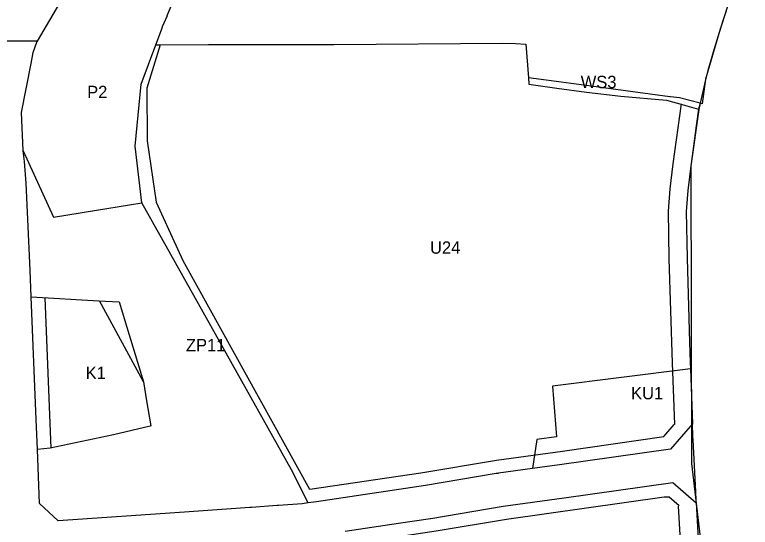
# Model space of a CAD drawing. Extents: x 7428103 to 7431580, y 5545880 to 5549002.
# Drawn here: x 7429886.6 to 7430217.3, y 5548057.7 to 5548288 of the extents above; entities that cross this region are included whole.
import ezdxf

# ---------------------------------------------------------------- set-up
doc = ezdxf.new("R2010")
doc.units = 0
for name, color, linetype in [('CZ_L_linie rozgraniczające tereny o różnym przeznaczeniu oraz różnych warunkach ich zabudowy i zagospodarowania', 7, 'Continuous'), ('CZ_L_maksymalne nieprzekraczalne linie zabudowy', 7, 'Continuous'), ('CZ_L_opisy_linie rozgraniczające tereny o różnym przeznaczeniu oraz różnych warunkach ich zabudowy i zagospodarowania', 7, 'Continuous'), ('Łąki_Nowohuckie', 7, 'Continuous')]:
    doc.layers.add(name, color=color, linetype=linetype)

msp = doc.modelspace()

# ---------------------------------------------------------------- linework, layer by layer
at = {"layer": 'CZ_L_linie rozgraniczające tereny o różnym przeznaczeniu oraz różnych warunkach ich zabudowy i zagospodarowania'}
for p, q in [((7429955.17, 5548287.65), (7429963.28, 5548306.64)), ((7429911.31, 5548300.91), (7429902.3, 5548285.56)), ((7430208.15, 5548295.69), (7430203.82, 5548281.96)), ((7429953.1, 5548282.8), (7429955.31, 5548287.65)), ((7429955.31, 5548287.65), (7429955.17, 5548287.65)), ((7429902.3, 5548285.56), (7429896.76, 5548276.15)), ((7429950.02, 5548274.53), (7429953.08, 5548282.4)), ((7429952.93, 5548282.41), (7429953.07, 5548282.8)), ((7429953.08, 5548282.4), (7429952.93, 5548282.41)), ((7429953.07, 5548282.8), (7429953.1, 5548282.8)), ((7430203.82, 5548281.96), (7430201.1, 5548272.72)), ((7429896.76, 5548276.15), (7429856.01, 5548276.02)), ((7429895.01, 5548271.04), (7429896.76, 5548276.15)), ((7429943.51, 5548256.83), (7429950.02, 5548274.53)), ((7429950.02, 5548274.53), (7429952.04, 5548274.53)), ((7429952.04, 5548274.53), (7429973.7, 5548274.58)), ((7429973.7, 5548274.58), (7430010.32, 5548274.66)), ((7430010.32, 5548274.66), (7430030.1, 5548274.7)), ((7430030.1, 5548274.7), (7430106, 5548275.27)), ((7430106, 5548275.27), (7430111.79, 5548275.03)), ((7430111.79, 5548275.03), (7430116.43, 5548274.83)), ((7430116.43, 5548274.83), (7430117.56, 5548259.73)), ((7429894.04, 5548266.06), (7429895.01, 5548271.04)), ((7430201.1, 5548272.72), (7430198.23, 5548262.99)), ((7429889.76, 5548244.08), (7429894.04, 5548266.06)), ((7430198.23, 5548262.99), (7430197.07, 5548258.75)), ((7430125.5, 5548258.65), (7430117.56, 5548259.73)), ((7430147.99, 5548255.62), (7430125.5, 5548258.65)), ((7430197.07, 5548258.75), (7430194.69, 5548248.36)), ((7429940.84, 5548228.99), (7429943.51, 5548256.83)), ((7430166.77, 5548253.11), (7430147.99, 5548255.62)), ((7430181.07, 5548251.2), (7430166.77, 5548253.11)), ((7430181.45, 5548251.13), (7430181.07, 5548251.2)), ((7430185.4, 5548250.61), (7430181.45, 5548251.13)), ((7430194.69, 5548248.36), (7430185.4, 5548250.61)), ((7430194.69, 5548248.36), (7430194.06, 5548245.59)), ((7429890.38, 5548227.06), (7429889.76, 5548244.08)), ((7430194.06, 5548245.59), (7430193.01, 5548238.09)), ((7430193.01, 5548238.09), (7430191.43, 5548226.76)), ((7429943.82, 5548203.5), (7429940.84, 5548228.99)), ((7429890.5, 5548226.8), (7429890.38, 5548227.06)), ((7429891.04, 5548222), (7429890.5, 5548226.8)), ((7429890.5, 5548226.8), (7429904.1, 5548197.11)), ((7430191.43, 5548226.76), (7430190.5, 5548220.15)), ((7429891.82, 5548212.26), (7429891.04, 5548222)), ((7430190.5, 5548220.15), (7430189.22, 5548209.03)), ((7429893.61, 5548173.2), (7429891.82, 5548212.26)), ((7430189.22, 5548209.03), (7430188.5, 5548199.62)), ((7429923.44, 5548200.17), (7429938.23, 5548202.63)), ((7429938.23, 5548202.63), (7429943.82, 5548203.5)), ((7429953.36, 5548186.48), (7429943.82, 5548203.5)), ((7429904.1, 5548197.11), (7429923.44, 5548200.17)), ((7430188.5, 5548199.62), (7430188.83, 5548178.55)), ((7429980.38, 5548138.29), (7429953.36, 5548186.48)), ((7430188.83, 5548178.55), (7430189.99, 5548140.74)), ((7429894.09, 5548161.22), (7429893.61, 5548173.2)), ((7429896.29, 5548106.13), (7429894.09, 5548161.22)), ((7429894.09, 5548161.22), (7429924.42, 5548159.49)), ((7429924.42, 5548159.49), (7429933.62, 5548158.97)), ((7429933.62, 5548158.97), (7429936.03, 5548150.99)), ((7429936.03, 5548150.99), (7429944.49, 5548123)), ((7430011.07, 5548083.54), (7429980.38, 5548138.29)), ((7430189.99, 5548140.74), (7430190.26, 5548131.75)), ((7430190.26, 5548131.75), (7430190.37, 5548128.86)), ((7430190.37, 5548128.86), (7430128.38, 5548121.04)), ((7430190.37, 5548128.86), (7430191.3, 5548104.13)), ((7429944.49, 5548123), (7429945.82, 5548114.54)), ((7430128.38, 5548121.04), (7430130.16, 5548098.26)), ((7429945.82, 5548114.54), (7429947.79, 5548103.21)), ((7429896.84, 5548092.61), (7429896.29, 5548106.13)), ((7429947.51, 5548103.15), (7429931.08, 5548099.27)), ((7429947.79, 5548103.21), (7429947.51, 5548103.15)), ((7430191.3, 5548104.13), (7430181.44, 5548092.75)), ((7430191.51, 5548098.46), (7430191.3, 5548104.13)), ((7429931.08, 5548099.27), (7429902.65, 5548093.16)), ((7430191.57, 5548096.98), (7430191.51, 5548098.46)), ((7430121.31, 5548097.17), (7430119.43, 5548084.03)), ((7430130.16, 5548098.26), (7430121.31, 5548097.17)), ((7430192.74, 5548073.53), (7430191.57, 5548096.98)), ((7429902.65, 5548093.16), (7429896.84, 5548092.61)), ((7429897.82, 5548068.32), (7429896.84, 5548092.61)), ((7430181.44, 5548092.75), (7430131.58, 5548085.69)), ((7430131.58, 5548085.69), (7430119.43, 5548084.03)), ((7430018.58, 5548068.58), (7430011.07, 5548083.54)), ((7430103.84, 5548081.89), (7430103.02, 5548081.76)), ((7430104.07, 5548081.93), (7430103.84, 5548081.89)), ((7430119.43, 5548084.03), (7430104.07, 5548081.93)), ((7430103.02, 5548081.76), (7430071.3, 5548076.41)), ((7430071.3, 5548076.41), (7430022.24, 5548069.12)), ((7430133.65, 5548070.84), (7430182.38, 5548077.74)), ((7430182.38, 5548077.74), (7430192.99, 5548068.68)), ((7430192.91, 5548070.03), (7430192.74, 5548073.53)), ((7430022.24, 5548069.12), (7430018.58, 5548068.58)), ((7430106.21, 5548067.08), (7430133.62, 5548070.83)), ((7430133.62, 5548070.83), (7430133.65, 5548070.84)), ((7430192.99, 5548068.68), (7430192.91, 5548070.03)), ((7430192.99, 5548068.68), (7430195.61, 5548021.96)), ((7429906.23, 5548060.63), (7429897.82, 5548068.32)), ((7429992.31, 5548066.53), (7429962.95, 5548064.49)), ((7429993.07, 5548066.59), (7429992.31, 5548066.53)), ((7430004.6, 5548067.39), (7429993.07, 5548066.59)), ((7430005.22, 5548067.43), (7430004.6, 5548067.39)), ((7430015.87, 5548068.17), (7430005.22, 5548067.43)), ((7430018.58, 5548068.58), (7430015.87, 5548068.17)), ((7430073.72, 5548061.61), (7430106.21, 5548067.08)), ((7429962.95, 5548064.49), (7429906.23, 5548060.63)), ((7430035.16, 5548055.88), (7430059.1, 5548059.44)), ((7430059.1, 5548059.44), (7430073.57, 5548061.59)), ((7430073.57, 5548061.59), (7430073.72, 5548061.61))]:
    msp.add_line(p, q, dxfattribs=at)
for points in [[(7430117.56, 5548259.73), (7430117.55, 5548259.73)], [(7430117.55, 5548259.73), (7430117.78, 5548256.79), (7430130.25, 5548255.01), (7430143.72, 5548253.16), (7430159.11, 5548251.49), (7430179.63, 5548249.59), (7430186.61, 5548247.65), (7430194.06, 5548245.59)]]:
    msp.add_lwpolyline(points, dxfattribs=at)
at = {"layer": 'CZ_L_maksymalne nieprzekraczalne linie zabudowy'}
for points in [[(7429952.08, 5548274.53), (7429946.08, 5548254.96), (7429946.22, 5548231.33), (7429950.28, 5548203.72), (7429962.18, 5548177.62), (7430019.07, 5548074.85)], [(7430183.3, 5548103.86), (7430182.27, 5548131.5), (7430180.84, 5548178.31), (7430180.5, 5548199.81), (7430181.25, 5548209.75), (7430182.55, 5548221.08), (7430186.4, 5548247.99)], [(7429900.11, 5548160.85), (7429902.82, 5548093.18)], [(7429944.49, 5548123), (7429924.73, 5548159.48)], [(7430019.23, 5548074.74), (7430069.16, 5548082.16), (7430103.17, 5548087.86), (7430132.86, 5548091.93), (7430178.48, 5548098.5), (7430183.12, 5548103.86)], [(7430185.29, 5548067.36), (7430180.79, 5548071.2), (7430178.6, 5548071.14), (7430107.69, 5548061.23), (7430076.06, 5548055.92), (7430039.24, 5548050.42), (7430038.47, 5548048.77), (7430038.85, 5548042.83)], [(7430154.46, 5547785.67), (7430173.26, 5547792.27), (7430193.23, 5547799.51), (7430194.45, 5547800.07), (7430198.73, 5547806.16), (7430199.09, 5547838.74), (7430198.96, 5547850.56), (7430197.64, 5547869.4), (7430193.56, 5547919.92), (7430185.06, 5548067.1)]]:
    msp.add_lwpolyline(points, dxfattribs=at)
at = {"layer": 'Łąki_Nowohuckie'}
for p, q in [((7430203.25, 5548280.01), (7430197.15, 5548259.12)), ((7430197.15, 5548259.12), (7430195.7, 5548248.02)), ((7430194.67, 5548248.27), (7430194.08, 5548245.49)), ((7430195.7, 5548248.02), (7430194.67, 5548248.27)), ((7430194.08, 5548245.49), (7430190.51, 5548220.05)), ((7430190.51, 5548220.05), (7430190.87, 5548086.36))]:
    msp.add_line(p, q, dxfattribs=at)
for points in [[(7430297.2, 5548430.43), (7430238.13, 5548349.75), (7430225.26, 5548330.6), (7430217.87, 5548316.02), (7430208.17, 5548295.59), (7430203.25, 5548280.01)], [(7430190.87, 5548086.36), (7430194.64, 5548054.47), (7430202.16, 5547988.55)]]:
    msp.add_lwpolyline(points, dxfattribs=at)

# ---------------------------------------------------------------- texts
at = {"layer": 'CZ_L_opisy_linie rozgraniczające tereny o różnym przeznaczeniu oraz różnych warunkach ich zabudowy i zagospodarowania'}
for s, p in [('WS3', (7430141.05, 5548255.04)), ('P2', (7429919.2, 5548250.55)), ('U24', (7430073.32, 5548180.61)), ('ZP11', (7429963.61, 5548136.76)), ('K1', (7429918.53, 5548124.3)), ('KU1', (7430163.68, 5548115.17))]:
    msp.add_text(s, height=5.549, dxfattribs=at).set_placement(p)

doc.saveas('drawing.dxf')
